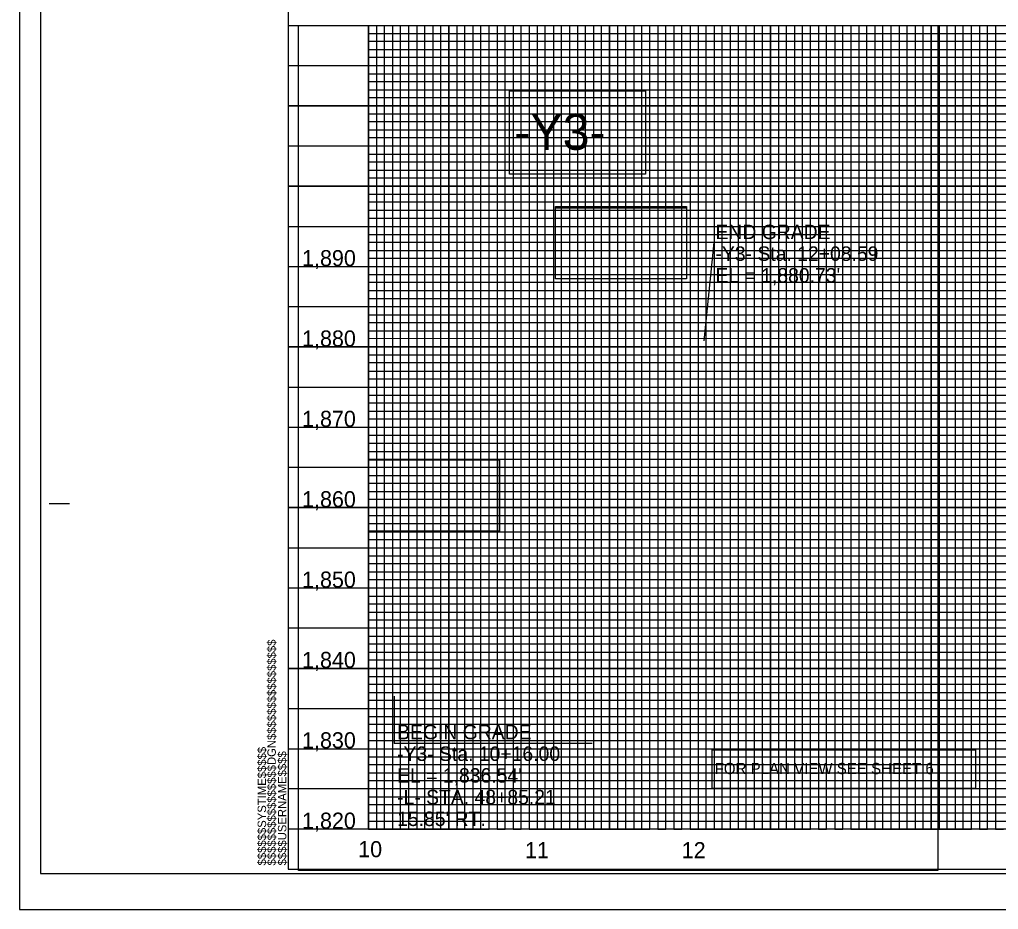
# Model space of a CAD drawing. Extents: x 557032 to 558840, y 515971 to 517218.
# Drawn here: x 557032 to 557641, y 516118 to 516672 of the extents above; entities that cross this region are included whole.
import ezdxf

# ---------------------------------------------------------------- set-up
doc = ezdxf.new("R2010")
doc.units = 0
for name, color, linetype in [('Exist Vertical Profile Horizontal Axis Label Major', 7, 'Continuous'), ('Exist Vertical Profile Vertical Axis Label', 7, 'Continuous'), ('Prop Vertical Profile Curve Label', 7, 'Continuous'), ('Prop Vertical Profile Grade Label', 7, 'Continuous'), ('Prop VPI Label', 7, 'Continuous'), ('Scratch_Level_5', 7, 'Continuous'), ('Sheet Cutting Line CELL', 7, 'Continuous'), ('Sheet DOT Grid CELL', 7, 'Continuous'), ('Sheet Layout Profile Border Port 2', 7, 'Continuous'), ('Sheet Plot Border Inside CELL', 7, 'Continuous'), ('Sheet Plot Border Outside CELL', 7, 'Continuous'), ('Sheet Profile CELL', 7, 'Continuous'), ('Sheet Profile Grid Major CELL', 7, 'Continuous'), ('Sheet Profile Grid Middle CELL', 7, 'Continuous'), ('Sheet Profile Grid Minor CELL', 7, 'Continuous')]:
    doc.layers.add(name, color=color, linetype=linetype)

msp = doc.modelspace()

# ---------------------------------------------------------------- linework, layer by layer
at = {"layer": 'Prop Vertical Profile Curve Label'}
msp.add_lwpolyline([(557337.11, 516627.51), (557421.69, 516627.51), (557421.69, 516575.56), (557337.11, 516575.56)], close=True, dxfattribs=at)
at = {"layer": 'Prop Vertical Profile Grade Label'}
for points in [[(557337.11, 516627.51), (557421.69, 516627.51), (557421.69, 516575.56), (557337.11, 516575.56)], [(557365.75, 516554.69), (557447.35, 516554.69), (557447.35, 516510.57), (557365.75, 516510.57)], [(557249.76, 516397.86), (557330.69, 516397.86), (557330.69, 516353.43), (557249.76, 516353.43)]]:
    msp.add_lwpolyline(points, close=True, dxfattribs=at)
at = {"layer": 'Prop VPI Label'}
for p, q in [((557464.23, 516533.14), (557458.04, 516471.86)), ((557586.78, 516533.14), (557464.23, 516533.14)), ((557265.45, 516250.91), (557265.47, 516221.5)), ((557388.52, 516221.5), (557265.47, 516221.5))]:
    msp.add_line(p, q, dxfattribs=at)
for points in [[(557337.11, 516627.51), (557421.69, 516627.51), (557421.69, 516575.56), (557337.11, 516575.56)], [(557365.75, 516555.49), (557447.35, 516555.49), (557447.35, 516510.57), (557365.75, 516510.57)], [(557249.45, 516398.17), (557331.05, 516398.17), (557331.05, 516353.24), (557249.45, 516353.24)], [(557463.24, 516217.52), (557626.94, 516217.52), (557626.94, 516193.4), (557463.24, 516193.4)], [(557463.24, 516217.52), (557626.94, 516217.52), (557626.94, 516193.4), (557463.24, 516193.4)]]:
    msp.add_lwpolyline(points, close=True, dxfattribs=at)
at = {"layer": 'Scratch_Level_5'}
msp.add_lwpolyline([(557205.94, 516668.17), (557603.68, 516668.17), (557603.68, 516142.39), (557205.94, 516142.39)], close=True, dxfattribs=at)
at = {"layer": 'Sheet Cutting Line CELL'}
for p, q in [((557032.45, 517218.17), (557032.45, 516118.17)), ((557032.45, 516118.17), (558716.45, 516118.17))]:
    msp.add_line(p, q, dxfattribs=at)
at = {"layer": 'Sheet DOT Grid CELL'}
for p, q in [((557199.45, 516668.17), (558699.34, 516668.17)), ((557249.45, 516668.17), (557249.45, 516168.17)), ((557299.45, 516668.17), (557299.45, 516168.17)), ((557349.45, 516668.17), (557349.45, 516168.17)), ((557399.45, 516668.17), (557399.45, 516168.17)), ((557449.45, 516668.17), (557449.45, 516168.17)), ((557499.45, 516668.17), (557499.45, 516168.17)), ((557549.45, 516668.17), (557549.45, 516168.17)), ((557599.45, 516668.17), (557599.45, 516168.17)), ((557199.45, 516618.17), (558699.34, 516618.17)), ((557199.45, 516568.17), (558699.34, 516568.17)), ((557199.45, 516518.17), (558699.34, 516518.17)), ((557199.45, 516468.17), (558699.34, 516468.17)), ((557199.45, 516418.17), (558699.34, 516418.17)), ((557199.45, 516368.17), (558699.34, 516368.17)), ((557199.45, 516318.17), (558699.34, 516318.17)), ((557199.45, 516268.17), (558699.34, 516268.17)), ((557199.45, 516218.17), (558699.34, 516218.17))]:
    msp.add_line(p, q, dxfattribs=at)
at = {"layer": 'Sheet Layout Profile Border Port 2'}
msp.add_lwpolyline([(557249.45, 516668.17), (558649.45, 516668.17), (558649.45, 516168.17), (557249.45, 516168.17)], close=True, dxfattribs=at)
at = {"layer": 'Sheet Plot Border Inside CELL'}
msp.add_lwpolyline([(557045.45, 516140.62), (558711.95, 516140.62), (558711.95, 517195.72), (557045.45, 517195.72)], close=True, dxfattribs=at)
at = {"layer": 'Sheet Plot Border Outside CELL'}
msp.add_lwpolyline([(557032.45, 516118.17), (558716.45, 516118.17), (558716.45, 517218.17), (557032.45, 517218.17)], close=True, dxfattribs=at)
at = {"layer": 'Sheet Profile CELL'}
for p, q in [((557199.45, 516668.17), (558699.45, 516668.17)), ((557050.95, 516370.67), (557063.45, 516370.67)), ((558699.45, 516168.17), (557199.45, 516168.17)), ((557199.45, 516143.17), (558699.45, 516143.17)), ((557199.45, 516143.17), (557199.45, 516143.17)), ((557199.45, 516143.17), (557199.45, 516143.17)), ((557199.45, 516143.17), (557199.45, 516143.17)), ((557199.45, 516143.17), (557199.45, 516143.17)), ((557199.45, 516143.17), (557199.45, 516143.17)), ((557199.45, 516143.17), (557199.45, 516143.17)), ((557199.45, 516143.17), (557199.45, 516143.17))]:
    msp.add_line(p, q, dxfattribs=at)
msp.add_lwpolyline([(558699.45, 517193.17), (557199.45, 517193.17), (557199.45, 516143.17), (558699.45, 516143.17)], close=True, dxfattribs=at)
msp.add_lwpolyline([(557236.95, 516143.17), (557236.95, 516143.17)], dxfattribs=at)
at = {"layer": 'Sheet Profile Grid Major CELL'}
msp.add_line((557199.45, 516168.17), (557199.45, 516168.17), dxfattribs=at)
for points in [[(557249.45, 516668.17), (557249.45, 516168.17), (557299.45, 516168.17), (557299.45, 516668.17), (557349.45, 516668.17), (557349.45, 516168.17), (557399.45, 516168.17), (557399.45, 516668.17), (557449.45, 516668.17), (557449.45, 516168.17), (557499.45, 516168.17), (557499.45, 516668.17), (557549.45, 516668.17), (557549.45, 516168.17), (557599.45, 516168.17), (557599.45, 516668.17), (557649.45, 516668.17)], [(558699.45, 516618.17), (557199.45, 516618.17)], [(558699.45, 516568.17), (557199.45, 516568.17), (557199.45, 516518.17), (558699.45, 516518.17)], [(558699.45, 516468.17), (557199.45, 516468.17), (557199.45, 516418.17), (558699.45, 516418.17)], [(558699.45, 516368.17), (557199.45, 516368.17), (557199.45, 516318.17), (558699.45, 516318.17)], [(558559.12, 516268.17), (557199.45, 516268.17), (557199.45, 516268.17), (557199.45, 516218.17), (558699.45, 516218.17)], [(558699.45, 516168.17), (557199.45, 516168.17)]]:
    msp.add_lwpolyline(points, dxfattribs=at)
at = {"layer": 'Sheet Profile Grid Middle CELL'}
for p, q in [((557224.45, 516668.17), (557274.45, 516668.17)), ((557274.45, 516668.17), (557274.45, 516168.17)), ((557324.45, 516168.17), (557324.45, 516668.17)), ((557324.45, 516668.17), (557374.45, 516668.17)), ((557374.45, 516668.17), (557374.45, 516168.17)), ((557424.45, 516168.17), (557424.45, 516668.17)), ((557424.45, 516668.17), (557474.45, 516668.17)), ((557474.45, 516668.17), (557474.45, 516168.17)), ((557524.45, 516168.17), (557524.45, 516668.17)), ((557524.45, 516668.17), (557574.45, 516668.17)), ((557574.45, 516668.17), (557574.45, 516168.17)), ((557624.45, 516168.17), (557624.45, 516668.17)), ((557624.45, 516668.17), (557674.45, 516668.17)), ((557274.45, 516168.17), (557324.45, 516168.17)), ((557374.45, 516168.17), (557424.45, 516168.17)), ((557474.45, 516168.17), (557524.45, 516168.17)), ((557574.45, 516168.17), (557624.45, 516168.17))]:
    msp.add_line(p, q, dxfattribs=at)
for points in [[(557199.45, 516643.17), (558699.45, 516643.17)], [(558699.45, 516593.17), (557199.45, 516593.17), (557199.45, 516543.17), (558699.45, 516543.17)], [(558699.45, 516493.17), (557199.45, 516493.17), (557199.45, 516443.17), (558699.45, 516443.17)], [(558699.45, 516393.17), (557199.45, 516393.17), (557199.45, 516343.17), (558699.45, 516343.17)], [(558699.45, 516293.17), (557199.45, 516293.17), (557199.45, 516243.17), (558699.45, 516243.17)], [(558699.45, 516193.17), (557199.45, 516193.17)]]:
    msp.add_lwpolyline(points, dxfattribs=at)
at = {"layer": 'Sheet Profile Grid Minor CELL'}
for p, q in [((557469.45, 516168.17), (557469.45, 516668.17)), ((557469.45, 516668.17), (557479.45, 516668.17)), ((557479.45, 516668.17), (557479.45, 516168.17)), ((557484.45, 516168.17), (557484.45, 516668.17)), ((557484.45, 516668.17), (557489.45, 516668.17)), ((557489.45, 516668.17), (557489.45, 516168.17)), ((557494.45, 516168.17), (557494.45, 516668.17)), ((557494.45, 516668.17), (557504.45, 516668.17)), ((557504.45, 516668.17), (557504.45, 516168.17)), ((557509.45, 516168.17), (557509.45, 516668.17)), ((557509.45, 516668.17), (557514.45, 516668.17)), ((557514.45, 516668.17), (557514.45, 516168.17)), ((557519.45, 516168.17), (557519.45, 516668.17)), ((557519.45, 516668.17), (557529.45, 516668.17)), ((557529.45, 516668.17), (557529.45, 516168.17)), ((557534.45, 516168.17), (557534.45, 516668.17)), ((557534.45, 516668.17), (557539.45, 516668.17)), ((557539.45, 516668.17), (557539.45, 516168.17)), ((557544.45, 516168.17), (557544.45, 516668.17)), ((557544.45, 516668.17), (557554.45, 516668.17)), ((557554.45, 516668.17), (557554.45, 516168.17)), ((557559.45, 516168.17), (557559.45, 516668.17)), ((557559.45, 516668.17), (557564.45, 516668.17)), ((557564.45, 516668.17), (557564.45, 516168.17)), ((557569.45, 516168.17), (557569.45, 516668.17)), ((557569.45, 516668.17), (557579.45, 516668.17)), ((557579.45, 516668.17), (557579.45, 516168.17)), ((557584.45, 516168.17), (557584.45, 516668.17)), ((557584.45, 516668.17), (557589.45, 516668.17)), ((557589.45, 516668.17), (557589.45, 516168.17)), ((557594.45, 516168.17), (557594.45, 516668.17)), ((557594.45, 516668.17), (557604.45, 516668.17)), ((557604.45, 516668.17), (557604.45, 516168.17)), ((557609.45, 516168.17), (557609.45, 516668.17)), ((557609.45, 516668.17), (557614.45, 516668.17)), ((557614.45, 516668.17), (557614.45, 516168.17)), ((557619.45, 516168.17), (557619.45, 516668.17)), ((557619.45, 516668.17), (557629.45, 516668.17)), ((557629.45, 516668.17), (557629.45, 516168.17)), ((557634.45, 516168.17), (557634.45, 516668.17)), ((557634.45, 516668.17), (557639.45, 516668.17)), ((557639.45, 516668.17), (557639.45, 516168.17)), ((557249.45, 516663.17), (558649.45, 516663.17)), ((558649.45, 516658.17), (557249.45, 516658.17)), ((557249.45, 516653.17), (558649.45, 516653.17)), ((558649.45, 516648.17), (557249.45, 516648.17)), ((557249.45, 516638.17), (558649.45, 516638.17)), ((558649.45, 516633.17), (557249.45, 516633.17)), ((557249.45, 516628.17), (558649.45, 516628.17)), ((558649.45, 516623.17), (557249.45, 516623.17)), ((557249.45, 516613.17), (558649.45, 516613.17)), ((558649.45, 516608.17), (557249.45, 516608.17)), ((557249.45, 516603.17), (558649.45, 516603.17)), ((558649.45, 516598.17), (557249.45, 516598.17)), ((557249.45, 516588.17), (558649.45, 516588.17)), ((558649.45, 516583.17), (557249.45, 516583.17)), ((557249.45, 516578.17), (558649.45, 516578.17)), ((558649.45, 516573.17), (557249.45, 516573.17)), ((557249.45, 516563.17), (558649.45, 516563.17)), ((558649.45, 516558.17), (557249.45, 516558.17)), ((557249.45, 516553.17), (558649.45, 516553.17)), ((558649.45, 516548.17), (557249.45, 516548.17)), ((557249.45, 516538.17), (558649.45, 516538.17)), ((558649.45, 516533.17), (557249.45, 516533.17)), ((557249.45, 516528.17), (558649.45, 516528.17)), ((558649.45, 516523.17), (557249.45, 516523.17)), ((557249.45, 516513.17), (558649.45, 516513.17)), ((558649.45, 516508.17), (557249.45, 516508.17)), ((557249.45, 516503.17), (558649.45, 516503.17)), ((558649.45, 516498.17), (557249.45, 516498.17)), ((557249.45, 516488.17), (558649.45, 516488.17)), ((558649.45, 516483.17), (557249.45, 516483.17)), ((557249.45, 516478.17), (558649.45, 516478.17)), ((558649.45, 516473.17), (557249.45, 516473.32)), ((557249.45, 516463.17), (558649.45, 516463.17)), ((558649.45, 516458.17), (557249.45, 516458.17)), ((557249.45, 516453.17), (558649.45, 516453.17)), ((558649.45, 516448.17), (557249.45, 516448.17)), ((557249.45, 516438.17), (558649.45, 516438.17)), ((558649.45, 516433.17), (557249.45, 516433.17)), ((557249.45, 516428.17), (558649.45, 516428.17)), ((558649.45, 516423.17), (557249.45, 516423.17)), ((557249.45, 516413.17), (558649.45, 516413.17)), ((558649.45, 516408.17), (557249.45, 516408.17)), ((557249.45, 516403.17), (558649.45, 516403.17)), ((558649.45, 516398.17), (557249.45, 516398.17)), ((557249.45, 516388.17), (558649.45, 516388.17)), ((558649.45, 516383.17), (557249.45, 516383.17)), ((557249.45, 516378.17), (558649.45, 516378.17)), ((558649.45, 516373.17), (557249.45, 516373.17)), ((557249.45, 516363.17), (558649.45, 516363.17)), ((558649.45, 516358.17), (557249.45, 516358.17)), ((557249.45, 516353.17), (558649.45, 516353.17)), ((558649.45, 516348.17), (557249.45, 516348.17)), ((557249.45, 516338.17), (558649.45, 516338.17)), ((558649.45, 516333.17), (557249.45, 516333.17)), ((557249.45, 516328.17), (558649.45, 516328.17)), ((558649.45, 516323.17), (557249.45, 516323.17)), ((557249.45, 516313.17), (558649.45, 516313.17)), ((558649.45, 516308.17), (557249.45, 516308.17)), ((557249.45, 516303.17), (558649.45, 516303.17)), ((558649.45, 516298.17), (557249.45, 516298.17)), ((557249.45, 516288.17), (558559.12, 516288.17)), ((558559.12, 516283.17), (557249.45, 516283.17)), ((557249.45, 516278.17), (558559.12, 516278.17)), ((558559.12, 516273.17), (557249.45, 516273.17)), ((557249.45, 516263.17), (558649.45, 516263.17)), ((558649.45, 516258.17), (557249.45, 516258.17)), ((557249.45, 516253.17), (558649.45, 516253.17)), ((558649.45, 516248.17), (557249.45, 516248.17)), ((557249.45, 516238.17), (558649.45, 516238.17)), ((558649.45, 516233.17), (557249.45, 516233.17)), ((557249.45, 516228.17), (558649.45, 516228.17)), ((558649.45, 516223.17), (557249.45, 516223.17)), ((557249.45, 516213.17), (558649.45, 516213.17)), ((558649.45, 516208.17), (557249.45, 516208.17)), ((557249.45, 516203.17), (558649.45, 516203.17)), ((558649.45, 516198.17), (557249.45, 516198.17)), ((557249.45, 516188.17), (558649.45, 516188.17)), ((558649.45, 516183.17), (557249.45, 516183.17)), ((557249.45, 516178.17), (558649.45, 516178.17)), ((557249.45, 516173.17), (558649.45, 516173.17)), ((557464.45, 516168.17), (557469.45, 516168.17)), ((557479.45, 516168.17), (557484.45, 516168.17)), ((557489.45, 516168.17), (557494.45, 516168.17)), ((557504.45, 516168.17), (557509.45, 516168.17)), ((557514.45, 516168.17), (557519.45, 516168.17)), ((557529.45, 516168.17), (557534.45, 516168.17)), ((557539.45, 516168.17), (557544.45, 516168.17)), ((557554.45, 516168.17), (557559.45, 516168.17)), ((557564.45, 516168.17), (557569.45, 516168.17)), ((557579.45, 516168.17), (557584.45, 516168.17)), ((557589.45, 516168.17), (557594.45, 516168.17)), ((557604.45, 516168.17), (557609.45, 516168.17)), ((557614.45, 516168.17), (557619.45, 516168.17)), ((557629.45, 516168.17), (557634.45, 516168.17)), ((557639.45, 516168.17), (557644.45, 516168.17))]:
    msp.add_line(p, q, dxfattribs=at)
for points in [[(557249.45, 516668.17), (557254.45, 516668.17), (557254.45, 516168.17), (557259.45, 516168.17), (557259.45, 516668.17), (557264.45, 516668.17), (557264.45, 516168.17), (557269.45, 516168.17), (557269.45, 516668.17), (557279.45, 516668.17), (557279.45, 516168.17), (557284.45, 516168.17), (557284.45, 516668.17), (557289.45, 516668.17), (557289.45, 516168.17), (557294.45, 516168.17), (557304.45, 516168.17), (557309.45, 516168.17), (557309.45, 516668.17), (557314.45, 516668.17), (557314.45, 516168.17), (557319.45, 516168.17), (557319.45, 516668.17), (557329.45, 516668.17), (557329.45, 516168.17), (557334.45, 516168.17), (557334.45, 516668.17), (557339.45, 516668.17), (557339.45, 516168.17), (557344.45, 516168.17), (557344.45, 516668.17), (557354.45, 516668.17), (557354.45, 516168.17), (557359.45, 516168.17), (557359.45, 516668.17), (557364.45, 516668.17), (557364.45, 516168.17), (557369.45, 516168.17), (557369.45, 516668.17), (557379.45, 516668.17), (557379.45, 516168.17), (557384.45, 516168.17), (557384.45, 516668.17), (557389.45, 516668.17), (557389.45, 516168.17), (557394.45, 516168.17), (557394.45, 516668.17), (557404.45, 516668.17), (557404.45, 516168.17), (557409.45, 516168.17), (557409.45, 516668.17), (557414.45, 516668.17), (557414.45, 516168.17), (557419.45, 516168.17), (557419.45, 516668.17), (557429.45, 516668.17), (557429.45, 516168.17), (557434.45, 516168.17), (557434.45, 516668.17), (557439.45, 516668.17), (557439.45, 516168.17), (557444.45, 516168.17), (557444.45, 516668.17), (557454.45, 516668.17), (557454.45, 516168.17), (557459.45, 516168.17), (557459.45, 516668.17), (557464.45, 516668.17), (557464.45, 516168.17)], [(557294.45, 516168.17), (557294.45, 516668.17), (557304.45, 516668.17), (557304.45, 516168.17)]]:
    msp.add_lwpolyline(points, dxfattribs=at)

# ---------------------------------------------------------------- texts
at = {"layer": 'Exist Vertical Profile Horizontal Axis Label Major'}
for s, p in [('10', (557243.07, 516150.67)), ('11', (557346.79, 516150.04)), ('12', (557444.31, 516150.04))]:
    msp.add_text(s, height=10, dxfattribs=at).set_placement(p)
at = {"layer": 'Exist Vertical Profile Vertical Axis Label'}
for s, p in [('1,890', (557208.15, 516518.42)), ('1,880', (557208.15, 516468.42)), ('1,870', (557208.15, 516418.42)), ('1,860', (557208.15, 516368.42)), ('1,850', (557208.15, 516318.42)), ('1,840', (557208.15, 516268.42)), ('1,830', (557208.15, 516218.42)), ('1,820', (557208.15, 516168.42))]:
    msp.add_text(s, height=10, dxfattribs=at).set_placement(p)
at = {"layer": 'Prop Vertical Profile Grade Label'}
msp.add_text('-Y3-', height=22.5, dxfattribs=at).set_placement((557340.14, 516590.78))
at = {"layer": 'Prop VPI Label'}
for s, height, p in [('END GRADE ', 9, (557465.29, 516535.21)), ('-Y3- Sta. 12+08.59', 9, (557465.29, 516521.71)), ("EL = 1,880.73'", 9, (557465.29, 516508.21)), ('BEGIN GRADE ', 9, (557267.28, 516224.06)), ('-Y3- Sta. 10+16.00', 9, (557267.28, 516210.56)), ('FOR PLAN VIEW SEE SHEET 6', 7, (557464.79, 516202.34)), ("EL = 1,836.54'", 9, (557267.28, 516197.06)), ('-L- STA. 48+85.21', 9, (557267.28, 516183.56)), ("15.85' RT.", 9, (557267.28, 516170.06))]:
    msp.add_text(s, height=height, dxfattribs=at).set_placement(p)
at = {"layer": 'Sheet Profile CELL'}
for s, p in [('$$$$$$$$$$$$$$$$DGN$$$$$$$$$$$$$$$$', (557191.82, 516145.54)), ('$$$$$$SYSTIME$$$$$', (557185.77, 516145.54)), ('$$$$USERNAME$$$$', (557198.39, 516145.55))]:
    msp.add_text(s, height=5.25, rotation=90, dxfattribs=at).set_placement(p)

doc.saveas('drawing.dxf')
